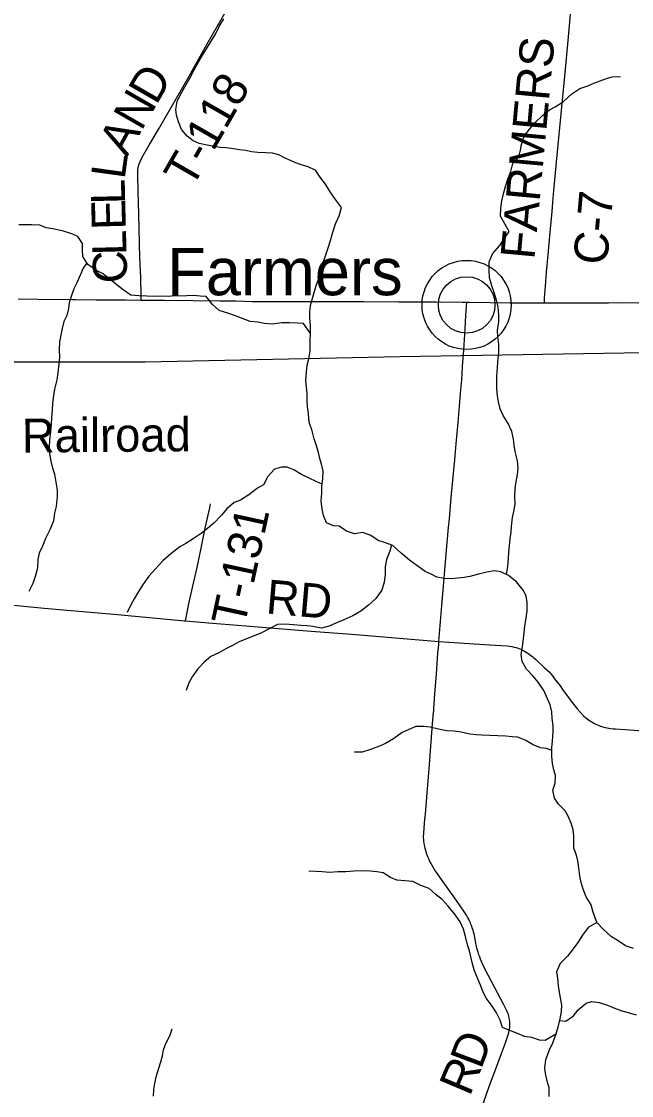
# Model space of a CAD drawing. Extents: x 1442749 to 1756758, y 235267 to 677782.
# Drawn here: x 1607177 to 1612553, y 476949 to 486415 of the extents above; entities that cross this region are included whole.
import ezdxf

# ---------------------------------------------------------------- set-up
doc = ezdxf.new("R2010")
doc.units = 0
for name, color, linetype in [('GM_X_County_Road', 7, 'Continuous'), ('GM_X_County_Road_Text', 7, 'Continuous'), ('GM_X_Major_River', 7, 'Continuous'), ('GM_X_Minor_River', 7, 'Continuous'), ('GM_X_Rail_Line', 7, 'Continuous'), ('GM_X_Rail_Line_Text', 7, 'Continuous'), ('GM_X_State_Route', 7, 'Continuous'), ('GM_X_Township_Road', 7, 'Continuous'), ('GM_X_Township_Road_Text', 7, 'Continuous'), ('GM_X_Unincorporated', 7, 'Continuous'), ('GM_X_Unincorporated_Location', 7, 'Continuous'), ('GM_X_Unincorporated_Text', 7, 'Continuous')]:
    doc.layers.add(name, color=color, linetype=linetype)

msp = doc.modelspace()

# ---------------------------------------------------------------- linework, layer by layer
at = {"layer": 'GM_X_County_Road'}
for points in [[(1611785.2, 483935.3), (1611788, 483977.6), (1611795, 484082), (1611805.6, 484206.2), (1611819.6, 484359.7), (1611836.4, 484559.1), (1611853.1, 484742), (1611859.3, 484820.5), (1611868, 484925), (1611898.3, 485238.5), (1611973.9, 486025.5), (1612004.9, 486345.5), (1612025.5, 486584.1), (1612035.9, 486701.7), (1612050.7, 486851.8), (1612063.5, 486992.3), (1612076.8, 487136), (1612114.8, 487541.1), (1612150.9, 487923), (1612169.5, 488125.6), (1612188.3, 488324.8), (1612217.9, 488651.5), (1612246.1, 488966.1)], [(1610856, 480951.2), (1610881.8, 481268.6), (1610896.4, 481438.3), (1610915, 481650.8), (1610929.4, 481824), (1610941.8, 481954.3), (1610948.6, 482032.7), (1610964.4, 482219), (1610995.3, 482552.1), (1611007, 482692.7), (1611025.4, 482882), (1611037.1, 483022.6), (1611046.8, 483140.3), (1611056.9, 483258), (1611064.9, 483375.8), (1611075.5, 483519.6), (1611087.6, 483706.3), (1611093.6, 483824.2), (1611098.8, 483902.5), (1611101.3, 483940.9)], [(1611227.3, 476825.4), (1611274.9, 476961.8), (1611303.1, 477038.7), (1611348.6, 477161.6), (1611408.2, 477321.1), (1611442.1, 477413.5), (1611466.4, 477485.3), (1611471.6, 477505.2), (1611475.6, 477520.5), (1611478.3, 477537), (1611480.5, 477550.1), (1611482.2, 477573.4), (1611482, 477588.8), (1611481.9, 477600.2), (1611478.8, 477623.4), (1611476.1, 477634.7), (1611473.4, 477646.3), (1611467.8, 477662.2), (1611463.4, 477674.5), (1611453.8, 477696.7), (1611446.3, 477714), (1611425.6, 477755.2), (1611318, 477954.4), (1611260.6, 478064.9), (1611250.7, 478085.4), (1611240.8, 478106.1), (1611231.1, 478129.6), (1611222.1, 478151.2), (1611215.2, 478170.3), (1611208.9, 478188), (1611201.6, 478211.6), (1611195.4, 478231.6), (1611191, 478249.2), (1611187.5, 478263.2), (1611184.2, 478278.2), (1611181.9, 478288.7), (1611178.1, 478309.8), (1611174.8, 478327.4), (1611165.6, 478372.6), (1611160.8, 478391.2), (1611156.4, 478407.8), (1611150, 478427.6), (1611145.2, 478442.4), (1611138.7, 478458.6), (1611134.1, 478470), (1611125.4, 478488.5), (1611118.5, 478502.9), (1611108.6, 478520.9), (1611099.3, 478537.7), (1611076.5, 478574), (1611011.2, 478668.5), (1610864.1, 478873.8), (1610837.2, 478912.8), (1610821.3, 478935.7), (1610807.8, 478957.6), (1610795.7, 478977.3), (1610786.7, 478993.9), (1610777.2, 479011.8), (1610768.7, 479030.1), (1610760.8, 479047.2), (1610754.8, 479062.6), (1610749, 479077.5), (1610743.9, 479094.2), (1610739.4, 479108.4), (1610735.3, 479125.3), (1610731, 479143.1), (1610728.4, 479157.1), (1610725.2, 479174.9), (1610723.4, 479192.1), (1610721.8, 479207.2), (1610721.4, 479221.5), (1610721, 479236.2), (1610721.8, 479252.3), (1610722.6, 479265.5), (1610731.9, 479386.2), (1610734, 479406.9), (1610736.3, 479428.8), (1610752.9, 479618.2), (1610769, 479827.4), (1610800.2, 480226.2), (1610808.8, 480325.5), (1610810.1, 480340.5), (1610811.2, 480357.8), (1610820, 480491), (1610834.1, 480664.1), (1610847.3, 480850.5), (1610853.9, 480925.6), (1610856, 480951.2)]]:
    msp.add_lwpolyline(points, dxfattribs=at)
at = {"layer": 'GM_X_Major_River'}
for points in [[(1612570.9, 478244.8), (1612501.2, 478268.3), (1612428.2, 478319.9), (1612376.6, 478346.9), (1612307.9, 478412.5), (1612247.1, 478475.8), (1612172, 478431.2), (1612120.4, 478362.1), (1612081.1, 478298.8), (1612031.5, 478229.7), (1611988.3, 478176.5), (1611924.8, 478111.6), (1611893.3, 478040.1), (1611900.1, 477983.9), (1611906.7, 477915.6), (1611915.6, 477859.3), (1611924.5, 477809.1), (1611935.2, 477746.7), (1611934.1, 477690.6), (1611920.7, 477624.8), (1611905.1, 477551), (1611887.8, 477491.2)], [(1611887.8, 477491.2), (1611858, 477409.7), (1611828.7, 477350.1), (1611794.8, 477262.6), (1611785.4, 477192.7), (1611792.3, 477142.5), (1611807, 477080.1), (1611823.8, 477019.6), (1611824.1, 476939.5)]]:
    msp.add_lwpolyline(points, dxfattribs=at)
at = {"layer": 'GM_X_Minor_River'}
for points in [[(1609723.8, 483665.7), (1609722.8, 483735.9), (1609719.6, 483800.1), (1609718.3, 483854.2), (1609723.1, 483912.3), (1609737.9, 483966.2), (1609756.7, 484026.1), (1609775.5, 484084), (1609798.5, 484151.8), (1609813.2, 484205.8), (1609834.3, 484283.6), (1609863.5, 484367.5), (1609882.4, 484429.3), (1609901.2, 484485.2), (1609922.2, 484557.1), (1609945.3, 484633), (1609976.3, 484702.7), (1609997.3, 484774.6), (1609944.1, 484847.4), (1609898.9, 484914.2), (1609855.7, 484982.9), (1609814.2, 485033.5), (1609769, 485104.3), (1609695.3, 485137.3), (1609643.3, 485152), (1609581.5, 485176.8), (1609501.7, 485209.9), (1609445.9, 485238.7), (1609390, 485253.5), (1609331.9, 485256.2), (1609259.7, 485259.2), (1609205.6, 485265.9), (1609153.7, 485278.6), (1609097.6, 485283.3), (1609045.6, 485292), (1608979.5, 485302.9), (1608927.4, 485305.6), (1608873.4, 485312.3), (1608799.4, 485329.3), (1608743.4, 485340), (1608691.5, 485362.7), (1608637.9, 485403.5), (1608588.6, 485464.3), (1608561.4, 485530.8), (1608544.1, 485589.1), (1608538.8, 485639.3), (1608549.8, 485709.3), (1608576.6, 485767.1), (1608617.7, 485838.7), (1608660.8, 485916.3), (1608697.9, 485990), (1608739, 486061.6), (1608773.8, 486119.3), (1608808.6, 486173), (1608847.7, 486242.6), (1608886.6, 486304.2), (1608919.6, 486372), (1608960.6, 486439.6)], [(1611450.3, 481541.8), (1611463.6, 481614.8), (1611470.5, 481682.9), (1611473.2, 481739), (1611477.9, 481793), (1611482.8, 481859.1), (1611491.6, 481913.1), (1611496.2, 481963.1), (1611505.3, 482043.2), (1611516, 482095.2), (1611526.9, 482161.2), (1611525.8, 482227.3), (1611526.7, 482299.5), (1611537.6, 482361.5), (1611548.4, 482419.5), (1611553.2, 482479.5), (1611548, 482541.7), (1611527, 482624.2), (1611519.8, 482682.4), (1611512.4, 482734.6), (1611497.3, 482803), (1611466.1, 482873.5), (1611420.9, 482942.2), (1611395.6, 483002.7), (1611382.4, 483063), (1611373.1, 483115.2), (1611365.9, 483181.5), (1611367.4, 483291.7), (1611372.3, 483363.8), (1611375, 483415.8), (1611384.1, 483493.9), (1611385.1, 483568), (1611376, 483638.3), (1611372.7, 483690.5), (1611383.7, 483770.5), (1611384.5, 483828.6), (1611377.5, 483900.9), (1611362.2, 483959.2), (1611343, 484027.6), (1611323.7, 484084), (1611300.6, 484156.4), (1611297.6, 484226.6), (1611298.5, 484296.7), (1611327.5, 484368.5), (1611392.7, 484441.8), (1611429.5, 484495.5), (1611476.5, 484563), (1611441.2, 484625.6), (1611400.1, 484698.3), (1611403, 484766.4), (1611409.9, 484834.5), (1611428.9, 484908.4), (1611443.7, 484960.3), (1611464.6, 485026.2), (1611489.5, 485092), (1611506.6, 485163.9), (1611559.5, 485221.3), (1611576.3, 485281.3), (1611583, 485331.3), (1611608, 485403.1), (1611657, 485468.6), (1611701.8, 485522.2), (1611768.9, 485587.4), (1611829.7, 485636.8), (1611880.2, 485664.1), (1611955.1, 485711.3), (1612026.1, 485778.5), (1612097, 485825.7), (1612167.5, 485848.8), (1612219.9, 485872.2), (1612278.3, 485891.5), (1612332.8, 485912.8), (1612383.1, 485926.2), (1612455.3, 485931.3)], [(1609723.8, 483665.7), (1609662.8, 483752.7), (1609608.7, 483755.4), (1609538.6, 483760.3), (1609470.4, 483759.2), (1609386, 483748.3), (1609317.9, 483753.2), (1609259.9, 483766), (1609191.8, 483770.8), (1609116, 483799.9), (1609064.1, 483820.6), (1608994.2, 483845.6), (1608920.3, 483868.6), (1608860.9, 483921.5), (1608805.7, 483992.3), (1608751.6, 483995), (1608693.5, 483999.8), (1608635.3, 483998.5), (1608579.1, 483995.3), (1608527, 483995.9), (1608472.8, 483992.6), (1608402.6, 483993.5), (1608336.4, 483992.4), (1608280.3, 483993.1), (1608210.1, 483996), (1608140, 484003), (1608072.4, 484049.9), (1608020.9, 484092.7), (1607955.4, 484143.6), (1607891.9, 484194.6), (1607838.1, 484221.3), (1607760.6, 484274.4), (1607717.4, 484343.1), (1607716.2, 484405.3), (1607714.9, 484457.4), (1607673.6, 484520.1), (1607621.8, 484544.8), (1607547.9, 484567.8), (1607453.9, 484587.1), (1607395.9, 484597.8), (1607338, 484620.6), (1607265.9, 484623.6), (1607211.7, 484622.3), (1607153.5, 484623)], [(1607752.1, 484287.9), (1607722, 484240.9), (1607697.2, 484185.1), (1607666.1, 484111.3), (1607639.4, 484059.5), (1607616.5, 483999.7), (1607597.6, 483935.8), (1607591, 483885.8), (1607576.1, 483823.8), (1607551.3, 483770.1), (1607534.5, 483708.1), (1607512.9, 483592.2), (1607509.9, 483520), (1607511, 483453.9), (1607506.3, 483397.8), (1607497.2, 483317.8), (1607488.4, 483257.8), (1607469.2, 483175.8), (1607456.2, 483099.8), (1607451.5, 483047.8), (1607446.7, 482989.7), (1607441.9, 482925.6), (1607439.1, 482867.6), (1607434.2, 482801.5), (1607425.2, 482729.4), (1607420.4, 482665.4), (1607423.6, 482605.2), (1607434.8, 482540.9), (1607448.1, 482490.6), (1607467.3, 482424.2), (1607480.4, 482353.9), (1607491.5, 482283.6), (1607492.8, 482227.5), (1607481.6, 482141.4), (1607468.8, 482081.5), (1607457.9, 482015.5), (1607430.9, 481941.7), (1607387.7, 481860), (1607362.7, 481792.2), (1607333.8, 481728.5), (1607321, 481674.5), (1607318, 481598.4), (1607297, 481524.5), (1607276.1, 481460.6), (1607241.1, 481390.9)], [(1612247.1, 478475.8), (1612213.7, 478574.5), (1612196.4, 478630.8), (1612155.2, 478699.5), (1612126, 478768), (1612110.7, 478826.4), (1612099.4, 478884.6), (1612088.4, 478956.9), (1612081.1, 479017.2), (1612067.8, 479067.4), (1612046.5, 479129.9), (1612045.3, 479188), (1612043.9, 479238.1), (1612038.6, 479290.3), (1612025.2, 479340.6), (1611998, 479405.1), (1611968.6, 479459.6), (1611909.2, 479518.5), (1611873.8, 479569), (1611860.7, 479641.4), (1611879.6, 479701.3), (1611884.5, 479769.4), (1611869.1, 479819.7), (1611855.8, 479876), (1611850.6, 479940.2), (1611851.6, 480016.3), (1611856.4, 480072.4), (1611863.5, 480154.5), (1611862.2, 480206.6), (1611853, 480272.9), (1611851.8, 480331), (1611836.5, 480393.3), (1611813.2, 480445.8), (1611782.1, 480520.3), (1611730.9, 480593.1), (1611685.4, 480645.8), (1611628.1, 480706.7), (1611590.9, 480773.3), (1611581.7, 480837.6), (1611594.8, 480923.6), (1611601.6, 480977.6), (1611608.3, 481029.7), (1611613, 481087.7), (1611624, 481155.7), (1611632.8, 481219.8), (1611633.8, 481295.9), (1611624.5, 481352.2), (1611599.2, 481404.6), (1611540, 481477.5), (1611470.5, 481532.5), (1611402.7, 481563.5), (1611344.7, 481574.3), (1611278.3, 481561.1), (1611205.9, 481544), (1611127.5, 481525), (1611077.2, 481513.6), (1611018.9, 481508.3), (1610968.7, 481503), (1610904.6, 481505.8), (1610838.6, 481516.7), (1610786.8, 481543.4), (1610735, 481568.1), (1610661.5, 481621.2), (1610595.9, 481668.1), (1610522.5, 481729.2), (1610449.2, 481798.3), (1610375.3, 481823.3), (1610319.4, 481842.1), (1610255.8, 481885), (1610186, 481912), (1610111.6, 481900.9), (1610041.7, 481921.9), (1609978.1, 481966.8), (1609928.1, 481971.4), (1609864.2, 481996.3), (1609839, 482060.8), (1609825.8, 482121.1), (1609818.6, 482187.3), (1609823.5, 482257.4), (1609824.3, 482317.5), (1609833.2, 482383.6), (1609836.1, 482451.7), (1609822.8, 482502), (1609807.5, 482562.3), (1609794.2, 482616.6), (1609773, 482683), (1609757.7, 482737.3), (1609738.6, 482807.7), (1609713.5, 482884.2), (1609706.5, 482960.5), (1609699.2, 483018.7), (1609696, 483080.8), (1609694.8, 483137), (1609689.5, 483193.2), (1609684.2, 483247.3), (1609689.3, 483325.5), (1609696.1, 483387.5), (1609708.9, 483443.5), (1609721.8, 483513.4), (1609721, 483601.6), (1609723.8, 483665.7)], [(1609826.9, 482336.5), (1609772.8, 482360.3), (1609711, 482391.2), (1609645.2, 482422.1), (1609577.6, 482463), (1609517.7, 482485.9), (1609467.6, 482488.5), (1609407.2, 482469.3), (1609348.2, 482403.9), (1609311.1, 482330.2), (1609256.6, 482300.8), (1609181.6, 482243.7), (1609106.8, 482196.5), (1609050.4, 482177.2), (1608985.4, 482120), (1608940.6, 482064.4), (1608873.5, 481995.1), (1608816.7, 481947.8), (1608762, 481902.4), (1608689.1, 481855.2), (1608624.4, 481814), (1608573.9, 481784.5), (1608492.9, 481723.5), (1608421.9, 481662.2), (1608358.8, 481590.9), (1608299.7, 481525.5), (1608248.7, 481456), (1608207.7, 481390.4), (1608168.8, 481326.8), (1608142, 481273), (1608107, 481205.3)], [(1610438.9, 481801.8), (1610424.5, 481746.5), (1610395.4, 481672.8), (1610382.5, 481608.8), (1610383.7, 481542.6), (1610372.7, 481474.6), (1610351.8, 481404.7), (1610300.7, 481331.2), (1610235.7, 481269.9), (1610166.8, 481218.7), (1610098.1, 481177.5), (1610017.4, 481142.5), (1609952.9, 481115.3), (1609888.3, 481086), (1609819.9, 481068.9), (1609745.9, 481081.9), (1609695.8, 481088.5), (1609641.7, 481091.2), (1609571.6, 481098.1), (1609501.5, 481103.1), (1609433.3, 481102), (1609360.6, 481062.8), (1609285.8, 481023.7), (1609219.3, 480996.5), (1609168.9, 480977.1), (1609102.4, 480949.9), (1609031.7, 480912.7), (1608979.2, 480887.4), (1608916.6, 480850.1), (1608845.9, 480818.9), (1608787.1, 480769.6), (1608732.2, 480710.2), (1608681.1, 480638.7), (1608652.4, 480586.9), (1608627.4, 480519.1)], [(1611851.3, 479990.3), (1611803.4, 480008.9), (1611751.3, 480013.6), (1611681.5, 480042.6), (1611621.8, 480079.4), (1611552, 480108.4), (1611501.9, 480111), (1611445.9, 480117.8), (1611235.4, 480126.5), (1611183.3, 480129.2), (1611127.2, 480133.9), (1611051.2, 480151), (1610989.2, 480159.8), (1610925, 480164.6), (1610853, 480179.6), (1610779.1, 480196.6), (1610727, 480201.3), (1610652.8, 480202.2), (1610584.2, 480173), (1610531.7, 480147.7), (1610454.8, 480094.5), (1610384.1, 480051.4), (1610331.6, 480028), (1610253, 479999), (1610178.5, 479975.9), (1610112.3, 479976.7)], [(1611887.8, 477491.2), (1611793.5, 477435.4), (1611743.4, 477436), (1611675.5, 477461), (1611611.4, 477469.8), (1611549.6, 477496.7), (1611481.8, 477521.6), (1611416, 477548.5), (1611394.8, 477614.9), (1611361.6, 477683.5), (1611326.2, 477738.1), (1611275, 477804.9), (1611243.7, 477867.5), (1611222.4, 477921.8), (1611197.1, 477984.3), (1611166, 478056.9), (1611148.8, 478123.2), (1611126.1, 478223.8), (1611106.7, 478276.1), (1611089.6, 478350.5), (1611072.4, 478414.9), (1611043.2, 478481.4), (1610994, 478550.2), (1610936.7, 478617.1), (1610883.4, 478675.9), (1610831.8, 478718.6), (1610770.3, 478773.6), (1610696.5, 478800.6), (1610626.8, 478835.6), (1610554.6, 478840.5), (1610486.5, 478847.4), (1610430.7, 478870.2), (1610365, 478911.1), (1610309, 478921.9), (1610248.9, 478926.6), (1610174.7, 478929.6), (1610106.5, 478926.5), (1610034.3, 478921.4), (1609966.1, 478920.3), (1609891.8, 478915.2), (1609825.7, 478922.1), (1609771.6, 478922.8), (1609709.4, 478925.6)], [(1611917.9, 477611.8), (1611974.2, 477605.4), (1612041, 477652.7), (1612083.8, 477704.2), (1612154.8, 477763.4), (1612205.1, 477776.8), (1612267.2, 477768), (1612343.1, 477747), (1612396.9, 477722.2), (1612466.8, 477695.3), (1612522.7, 477680.5), (1612594.7, 477659.5)], [(1608341.5, 476942.9), (1608342.3, 477003.1), (1608351, 477055.1), (1608363.8, 477115), (1608386.9, 477190.9), (1608405.7, 477246.8), (1608418.4, 477300.7), (1608429.1, 477352.7), (1608449.9, 477406.6), (1608484.9, 477476.3), (1608505.8, 477538.1)]]:
    msp.add_lwpolyline(points, dxfattribs=at)
at = {"layer": 'GM_X_Rail_Line'}
msp.add_lwpolyline([(1571148.2, 478363), (1571889, 478539.4), (1575743, 479318.6), (1579466.4, 480095.8), (1583642, 480977.8), (1587510.8, 481782.7), (1590381.5, 482358.7), (1593451.5, 482999.2), (1594964.1, 483308.1), (1595338.6, 483357), (1595650.3, 483378.6), (1596034.3, 483391.1), (1596556.5, 483384.9), (1598433.9, 483400.2), (1602127.8, 483416), (1606201.9, 483416.1), (1608266.9, 483417), (1610514.2, 483462.2), (1613925, 483518), (1615664.4, 483549), (1619432.2, 483601)], dxfattribs=at)
at = {"layer": 'GM_X_State_Route'}
for points in [[(1607147.1, 483970.2), (1607324.1, 483968.3), (1607629.3, 483963.9), (1607651.6, 483963.7)], [(1607651.6, 483963.7), (1607835.9, 483961.4), (1608095.1, 483961.2), (1608232.1, 483959.6), (1608311.6, 483958.6), (1608439.6, 483958.3), (1608688.8, 483955.2), (1608925, 483951.9), (1609069.4, 483951.8), (1609210.4, 483948.7), (1609308.9, 483948.3), (1609522.1, 483947.8), (1609709.1, 483948.3), (1610063.4, 483947), (1610191.3, 483947.1), (1610499.7, 483945.7), (1610634.2, 483945.9), (1610834.2, 483943.5), (1611060.6, 483941.7), (1611101.3, 483940.9), (1611126.1, 483940.4), (1611480.5, 483936.1), (1611542.8, 483936.2), (1611677.3, 483936.5), (1611785.2, 483935.3), (1611792.1, 483935.2), (1611869.7, 483935.2)], [(1611869.7, 483935.2), (1612054.6, 483935.2), (1612198.9, 483935.8), (1612284.2, 483935.6), (1612349.8, 483936.4), (1612438.3, 483937.8), (1612602.3, 483936.6), (1612746.7, 483937.6), (1613019, 483939.6), (1613189.5, 483939.2), (1613409.3, 483941.4), (1613448.8, 483941.4)]]:
    msp.add_lwpolyline(points, dxfattribs=at)
at = {"layer": 'GM_X_Township_Road'}
for points in [[(1608232.1, 483959.6), (1608231.3, 484000.8), (1608228.3, 484154.9), (1608221.2, 484338.4), (1608217.2, 484456.4), (1608213.5, 484597.4), (1608207.1, 484823.6), (1608204.6, 484912.1), (1608201.1, 485069.5), (1608202.6, 485102.2), (1608206.5, 485131.5), (1608214, 485160), (1608224.6, 485187.5), (1608237.9, 485213.9), (1608305.1, 485330.4), (1608386.1, 485469.2), (1608653.5, 485932), (1608814.2, 486218), (1608902.4, 486371.6), (1608988.5, 486522.6)], [(1608621.7, 481133), (1608627.9, 481162.8), (1608652.5, 481281.6), (1608685.7, 481425.6), (1608723.9, 481602.1), (1608760.8, 481772), (1608770.2, 481816.9), (1608796.1, 481949), (1608836.5, 482128.3), (1608843.1, 482163.6)], [(1601947.4, 481717.2), (1601979.8, 481715.1), (1602275.5, 481695.7), (1602929.3, 481639.7), (1603177.8, 481618.2), (1603396.7, 481598.6), (1604321.6, 481514.1), (1604802, 481473.1), (1605056.3, 481447), (1605962.8, 481368), (1606475.4, 481326.2), (1606687.9, 481308.1), (1606926.5, 481287.3), (1607377.4, 481246), (1608024, 481190), (1608613.2, 481133.6), (1608621.7, 481133)], [(1608621.7, 481133), (1608860.7, 481113.8), (1609155.6, 481088.8), (1609729.8, 481043), (1610086.6, 481015.5), (1610717.5, 480963.1), (1610854.7, 480951.3), (1610856, 480951.2)], [(1610856, 480951.2), (1611302.7, 480921.1), (1611456.5, 480911.5), (1611478.3, 480909.2), (1611499.7, 480906.4), (1611518.7, 480902.3), (1611535.8, 480898.1), (1611553.8, 480891.9), (1611569.3, 480885.5), (1611584.5, 480879.2), (1611598.3, 480872.1), (1611611.2, 480865.5), (1611626.1, 480856.5), (1611639.6, 480848.3), (1611652.4, 480839.1), (1611666.5, 480828.9), (1611679.5, 480818.1), (1611691.9, 480807.7), (1611709.6, 480791.3), (1611784.6, 480722.3), (1611826.5, 480683.3), (1611841, 480667), (1611856.6, 480647.5), (1611875.7, 480622.5), (1611924, 480560.8), (1611951.6, 480520.4), (1612041.6, 480399.4), (1612076, 480355.8), (1612103.9, 480323.9), (1612131.2, 480296.1), (1612150.6, 480278.9), (1612162.6, 480269.8), (1612173.8, 480261.2), (1612187.5, 480252.3), (1612198.2, 480245.2), (1612211.9, 480237.4), (1612226.4, 480229.1), (1612239.9, 480222.3), (1612252.5, 480216), (1612268.9, 480209.3), (1612279.5, 480205), (1612293.3, 480200.6), (1612307.1, 480196.2), (1612321.4, 480192.8), (1612338.7, 480188.8), (1612353.6, 480186.5), (1612370.7, 480183.8), (1612391.4, 480181.9), (1612412.9, 480179.8), (1612497.9, 480174.9), (1612694.4, 480162)]]:
    msp.add_lwpolyline(points, dxfattribs=at)
at = {"layer": 'GM_X_Unincorporated'}
for radius in [392.8, 249]:
    msp.add_circle((1611100.5, 483917.1), radius, dxfattribs=at)
at = {"layer": 'GM_X_Unincorporated_Location'}
msp.add_line((1611100.5, 483917.1), (1611100.5, 483917.1), dxfattribs=at)

# ---------------------------------------------------------------- texts
at = {"layer": 'GM_X_County_Road_Text'}
for s, rotation, p in [('FARMERS', 84.71264, (1611696.3, 484312.3)), ('C-7', 84.98588, (1612337.8, 484263.9)), ('D', 69.26239, (1611227.4, 477173.2)), ('R', 67.04688, (1611126.7, 476934.7))]:
    msp.add_text(s, height=300, rotation=rotation, dxfattribs=at).set_placement(p)
at = {"layer": 'GM_X_Rail_Line_Text'}
msp.add_text('Railroad', height=299, rotation=0.44957, dxfattribs=at).set_placement((1607181.5, 482616))
at = {"layer": 'GM_X_Township_Road_Text'}
for s, rotation, p in [('D', 59.99396, (1608365.2, 485671.4)), ('T-118', 60.18787, (1608678.4, 484934.2)), ('N', 59.99396, (1608233.1, 485442.8)), ('A', 61.25958, (1608107.1, 485212.9)), ('L', 82.19777, (1608085.6, 485017.9)), ('L', 91.3672, (1608091.7, 484806.2)), ('E', 91.51532, (1608097.6, 484582.1)), ('L', 91.51126, (1608103.5, 484357.8)), ('C', 91.50673, (1608110, 484111.4)), ('T-131', 77.77058, (1609141.7, 481072.8)), ('RD', 355.07189, (1609324.9, 481198.8))]:
    msp.add_text(s, height=300, rotation=rotation, dxfattribs=at).set_placement(p)
at = {"layer": 'GM_X_Unincorporated_Text'}
msp.add_text('Farmers', height=417, rotation=0.00001, dxfattribs=at).set_placement((1608461.1, 484002.6))

doc.saveas('drawing.dxf')
